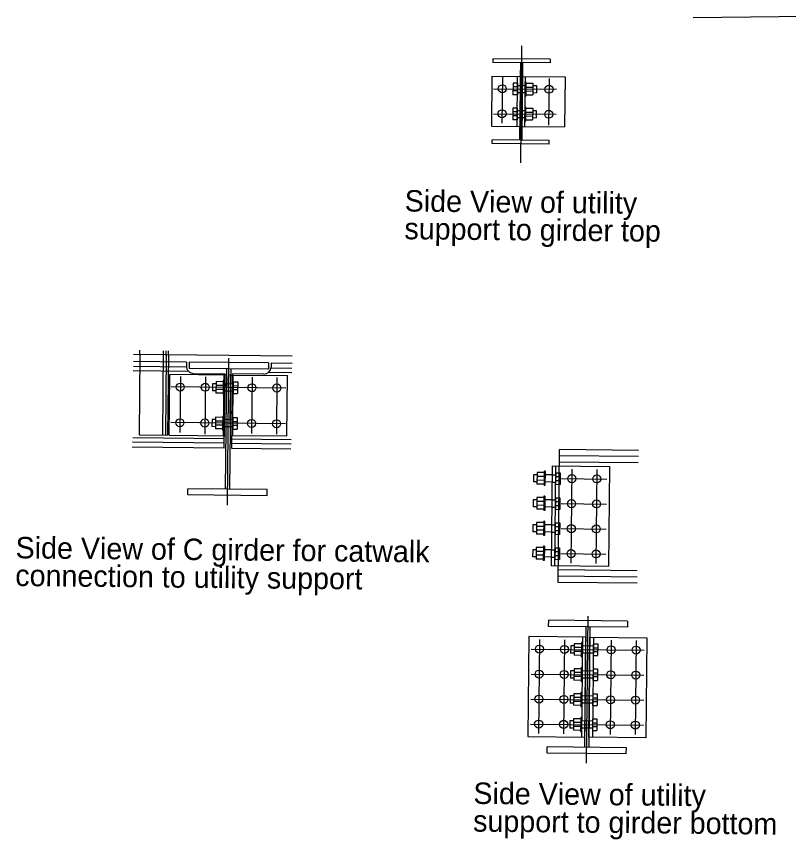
# Model space of a CAD drawing. Extents: x 632312 to 632425, y 378332 to 378413.
# Drawn here: x 632382.19 to 632391.2, y 378385.83 to 378395.43 of the extents above; entities that cross this region are included whole.
import ezdxf

# ---------------------------------------------------------------- set-up
doc = ezdxf.new("R2010")
doc.units = 0
for name, color, linetype in [('B_Boring', 7, 'Continuous'), ('B_Boring Annot', 7, 'Continuous'), ('R_Proposed Const Limits Cut', 7, 'Continuous'), ('R_Wall', 7, 'Continuous'), ('SHT_Dimensions', 7, 'Continuous'), ('USACE_Easement', 7, 'Continuous')]:
    doc.layers.add(name, color=color, linetype=linetype)

msp = doc.modelspace()

# ---------------------------------------------------------------- linework, layer by layer
at = {"layer": 'B_Boring'}
for p, q in [((632387.7503, 378394.9372), (632387.7498, 378394.8943)), ((632388.4177, 378394.9306), (632387.7503, 378394.9372)), ((632388.4173, 378394.8877), (632387.7498, 378394.8943)), ((632388.0713, 378394.8911), (632388.0623, 378393.9853)), ((632388.0959, 378394.8909), (632388.0869, 378393.9851)), ((632388.4177, 378394.9306), (632388.4173, 378394.8877)), ((632387.7382, 378394.7332), (632387.7324, 378394.1499)), ((632387.7382, 378394.7332), (632388.0697, 378394.7299)), ((632387.9855, 378394.6526), (632387.9842, 378394.5172)), ((632388.0376, 378394.6521), (632387.9855, 378394.6526)), ((632388.0326, 378394.1469), (632388.0384, 378394.7302)), ((632388.0376, 378394.6521), (632388.0363, 378394.5167)), ((632388.0943, 378394.7297), (632388.5923, 378394.7247)), ((632388.1255, 378394.7293), (632388.1197, 378394.146)), ((632388.1249, 378394.6668), (632388.1232, 378394.5002)), ((632388.1249, 378394.6668), (632388.1353, 378394.6667)), ((632388.1353, 378394.6667), (632388.1336, 378394.5001)), ((632388.1351, 378394.6511), (632388.2185, 378394.6503)), ((632388.2185, 378394.6503), (632388.2171, 378394.5149)), ((632388.5923, 378394.7247), (632388.5865, 378394.1414)), ((632388.0367, 378394.5618), (632387.9847, 378394.5623)), ((632388.0372, 378394.607), (632387.9851, 378394.6075)), ((632388.1342, 378394.5608), (632388.2176, 378394.56)), ((632388.1347, 378394.606), (632388.218, 378394.6052)), ((632388.2182, 378394.6242), (632388.2599, 378394.6238)), ((632388.2599, 378394.6238), (632388.259, 378394.5405)), ((632388.0363, 378394.5167), (632387.9842, 378394.5172)), ((632388.1232, 378394.5002), (632388.1336, 378394.5001)), ((632388.1338, 378394.5157), (632388.2171, 378394.5149)), ((632388.2174, 378394.5409), (632388.259, 378394.5405)), ((632387.9826, 378394.3609), (632387.9813, 378394.2255)), ((632388.0347, 378394.3604), (632387.9826, 378394.3609)), ((632388.122, 378394.3752), (632388.1203, 378394.2085)), ((632388.122, 378394.3752), (632388.1324, 378394.3751)), ((632388.1324, 378394.3751), (632388.1307, 378394.2084)), ((632388.0338, 378394.2701), (632387.9818, 378394.2706)), ((632388.0343, 378394.3153), (632387.9822, 378394.3158)), ((632388.0347, 378394.3604), (632388.0334, 378394.225)), ((632388.1313, 378394.2692), (632388.2147, 378394.2683)), ((632388.1318, 378394.3143), (632388.2151, 378394.3135)), ((632388.1322, 378394.3594), (632388.2156, 378394.3586)), ((632388.2156, 378394.3586), (632388.2142, 378394.2232)), ((632388.2153, 378394.3326), (632388.257, 378394.3321)), ((632388.257, 378394.3321), (632388.2561, 378394.2488)), ((632388.0334, 378394.225), (632387.9813, 378394.2255)), ((632388.1203, 378394.2085), (632388.1307, 378394.2084)), ((632388.1309, 378394.224), (632388.2142, 378394.2232)), ((632388.2145, 378394.2492), (632388.2561, 378394.2488)), ((632387.7324, 378394.1499), (632388.0639, 378394.1466)), ((632388.0885, 378394.1463), (632388.5865, 378394.1414)), ((632387.7404, 378393.9456), (632387.7408, 378393.9885)), ((632388.4083, 378393.9819), (632387.7408, 378393.9885)), ((632388.4079, 378393.939), (632388.4083, 378393.9819)), ((632388.4079, 378393.939), (632387.7404, 378393.9456)), ((632385.4086, 378391.4678), (632383.5584, 378391.4862)), ((632383.6308, 378391.4855), (632383.6313, 378391.5352)), ((632383.9381, 378391.4824), (632383.9385, 378391.529)), ((632383.9641, 378391.4821), (632383.9646, 378391.529)), ((632384.1753, 378391.3967), (632383.5576, 378391.4028)), ((632384.1753, 378391.3967), (632384.1748, 378391.3488)), ((632384.2065, 378391.3964), (632384.2058, 378391.3239)), ((632385.1315, 378391.3872), (632384.2065, 378391.3964)), ((632385.1315, 378391.3872), (632385.1307, 378391.3147)), ((632385.1627, 378391.3869), (632385.1622, 378391.339)), ((632385.1627, 378391.3869), (632385.4068, 378391.3845)), ((632384.1747, 378391.3384), (632383.5561, 378391.3445)), ((632385.1307, 378391.3147), (632384.2058, 378391.3239)), ((632384.632, 378389.9146), (632384.646, 378391.3195)), ((632384.6906, 378391.3191), (632384.6766, 378389.9141)), ((632385.1621, 378391.3286), (632385.4053, 378391.3261)), ((632383.973, 378390.5445), (632383.9801, 378391.2528)), ((632384.6452, 378391.2462), (632383.9801, 378391.2528)), ((632384.2573, 378391.2646), (632384.6245, 378391.261)), ((632384.6069, 378390.5382), (632384.614, 378391.2465)), ((632384.6159, 378390.3923), (632384.6245, 378391.261)), ((632384.6898, 378391.2457), (632385.355, 378391.2391)), ((632384.7108, 378391.2601), (632384.7022, 378390.3914)), ((632385.0781, 378391.2565), (632384.7108, 378391.2601)), ((632384.714, 378390.5371), (632384.7211, 378391.2454)), ((632385.3479, 378390.5308), (632385.355, 378391.2391)), ((632384.4775, 378391.1437), (632384.4767, 378391.0604)), ((632384.5192, 378391.1433), (632384.4775, 378391.1437)), ((632384.5195, 378391.1693), (632384.5181, 378391.0339)), ((632384.6023, 378391.1233), (632384.519, 378391.1242)), ((632384.6028, 378391.1685), (632384.5195, 378391.1693)), ((632384.6029, 378391.1841), (632384.6013, 378391.0175)), ((632384.6134, 378391.184), (632384.6029, 378391.1841)), ((632384.6134, 378391.184), (632384.6117, 378391.0173)), ((632384.7203, 378391.1673), (632384.7189, 378391.0319)), ((632384.7198, 378391.1222), (632384.7719, 378391.1217)), ((632384.7203, 378391.1673), (632384.7724, 378391.1668)), ((632384.7724, 378391.1668), (632384.771, 378391.0314)), ((632384.5184, 378391.0599), (632384.4767, 378391.0604)), ((632384.6014, 378391.0331), (632384.5181, 378391.0339)), ((632384.6019, 378391.0782), (632384.5186, 378391.079)), ((632384.6117, 378391.0173), (632384.6013, 378391.0175)), ((632384.7189, 378391.0319), (632384.771, 378391.0314)), ((632384.7194, 378391.077), (632384.7715, 378391.0765)), ((632384.4734, 378390.727), (632384.4726, 378390.6437)), ((632384.5151, 378390.7266), (632384.4734, 378390.727)), ((632384.5153, 378390.7527), (632384.514, 378390.6173)), ((632384.5986, 378390.7518), (632384.5153, 378390.7527)), ((632384.5988, 378390.7675), (632384.5971, 378390.6008)), ((632384.6092, 378390.7674), (632384.5988, 378390.7675)), ((632384.6092, 378390.7674), (632384.6076, 378390.6007)), ((632384.7162, 378390.7507), (632384.7148, 378390.6153)), ((632384.7162, 378390.7507), (632384.7682, 378390.7501)), ((632384.7682, 378390.7501), (632384.7669, 378390.6148)), ((632384.5142, 378390.6433), (632384.4726, 378390.6437)), ((632384.5973, 378390.6164), (632384.514, 378390.6173)), ((632384.5977, 378390.6616), (632384.5144, 378390.6624)), ((632384.5982, 378390.7067), (632384.5149, 378390.7075)), ((632384.7148, 378390.6153), (632384.7669, 378390.6148)), ((632384.7153, 378390.6604), (632384.7673, 378390.6599)), ((632384.7157, 378390.7055), (632384.7678, 378390.705)), ((632383.973, 378390.5445), (632384.6382, 378390.5379)), ((632384.6076, 378390.6007), (632384.5971, 378390.6008)), ((632385.3479, 378390.5308), (632384.6828, 378390.5375)), ((632384.6164, 378390.4506), (632383.5456, 378390.4613)), ((632384.7027, 378390.4497), (632385.3948, 378390.4429)), ((632384.6159, 378390.3923), (632383.5427, 378390.4029)), ((632384.7022, 378390.3914), (632385.3919, 378390.3846)), ((632388.5133, 378388.8256), (632388.5287, 378390.3756)), ((632389.4491, 378390.3664), (632388.5287, 378390.3756)), ((632389.4483, 378390.2939), (632388.528, 378390.3031)), ((632388.4435, 378390.1847), (632388.4319, 378389.0181)), ((632388.4435, 378390.1847), (632389.1101, 378390.1781)), ((632388.4735, 378389.0177), (632388.4851, 378390.1843)), ((632389.1101, 378390.1781), (632389.0985, 378389.0115)), ((632388.2237, 378390.0828), (632388.2229, 378389.9994)), ((632388.2654, 378390.0823), (632388.2237, 378390.0828)), ((632388.2656, 378390.1084), (632388.2643, 378389.973)), ((632388.3485, 378390.0624), (632388.2652, 378390.0632)), ((632388.349, 378390.1075), (632388.2656, 378390.1084)), ((632388.3491, 378390.1232), (632388.3475, 378389.9565)), ((632388.3595, 378390.1231), (632388.3491, 378390.1232)), ((632388.3595, 378390.1231), (632388.3579, 378389.9564)), ((632388.4424, 378390.0806), (632388.3591, 378390.0814)), ((632388.4839, 378390.0611), (632388.536, 378390.0606)), ((632388.4844, 378390.1062), (632388.5364, 378390.1057)), ((632388.5364, 378390.1057), (632388.5351, 378389.9703)), ((632388.2645, 378389.999), (632388.2229, 378389.9994)), ((632388.3476, 378389.9722), (632388.2643, 378389.973)), ((632388.3481, 378390.0173), (632388.2647, 378390.0181)), ((632388.3579, 378389.9564), (632388.3475, 378389.9565)), ((632388.4416, 378389.9973), (632388.3583, 378389.9981)), ((632388.483, 378389.9708), (632388.5351, 378389.9703)), ((632388.4835, 378390.0159), (632388.5356, 378390.0154)), ((632384.1911, 378389.8465), (632384.1918, 378389.919)), ((632385.1168, 378389.9098), (632384.1918, 378389.919)), ((632385.116, 378389.8373), (632385.1168, 378389.9098)), ((632385.116, 378389.8373), (632384.1911, 378389.8465)), ((632388.2208, 378389.7911), (632388.22, 378389.7078)), ((632388.2625, 378389.7907), (632388.2208, 378389.7911)), ((632388.2627, 378389.8167), (632388.2614, 378389.6813)), ((632388.3456, 378389.7708), (632388.2623, 378389.7716)), ((632388.3461, 378389.8159), (632388.2627, 378389.8167)), ((632388.3462, 378389.8315), (632388.3446, 378389.6649)), ((632388.3566, 378389.8314), (632388.3462, 378389.8315)), ((632388.3566, 378389.8314), (632388.355, 378389.6648)), ((632388.4395, 378389.7889), (632388.3562, 378389.7898)), ((632388.481, 378389.7694), (632388.5331, 378389.7689)), ((632388.4815, 378389.8145), (632388.5335, 378389.814)), ((632388.5335, 378389.814), (632388.5322, 378389.6786)), ((632388.2616, 378389.7074), (632388.22, 378389.7078)), ((632388.3447, 378389.6805), (632388.2614, 378389.6813)), ((632388.3452, 378389.7256), (632388.2618, 378389.7265)), ((632388.355, 378389.6648), (632388.3446, 378389.6649)), ((632388.4387, 378389.7056), (632388.3554, 378389.7064)), ((632388.4801, 378389.6792), (632388.5322, 378389.6786)), ((632388.4806, 378389.7243), (632388.5327, 378389.7238)), ((632388.2179, 378389.4995), (632388.2171, 378389.4161)), ((632388.2596, 378389.499), (632388.2179, 378389.4995)), ((632388.2598, 378389.5251), (632388.2585, 378389.3897)), ((632388.3427, 378389.4791), (632388.2594, 378389.4799)), ((632388.3432, 378389.5242), (632388.2598, 378389.5251)), ((632388.3433, 378389.5399), (632388.3417, 378389.3732)), ((632388.3537, 378389.5398), (632388.3433, 378389.5399)), ((632388.3537, 378389.5398), (632388.3521, 378389.3731)), ((632388.4366, 378389.4973), (632388.3533, 378389.4981)), ((632388.4781, 378389.4778), (632388.5302, 378389.4772)), ((632388.4786, 378389.5229), (632388.5306, 378389.5224)), ((632388.5306, 378389.5224), (632388.5293, 378389.387)), ((632388.2587, 378389.4157), (632388.2171, 378389.4161)), ((632388.3418, 378389.3888), (632388.2585, 378389.3897)), ((632388.3423, 378389.434), (632388.2589, 378389.4348)), ((632388.3521, 378389.3731), (632388.3417, 378389.3732)), ((632388.4358, 378389.4139), (632388.3525, 378389.4148)), ((632388.4772, 378389.3875), (632388.5293, 378389.387)), ((632388.4777, 378389.4326), (632388.5298, 378389.4321)), ((632388.215, 378389.2078), (632388.2142, 378389.1245)), ((632388.2567, 378389.2074), (632388.215, 378389.2078)), ((632388.2569, 378389.2334), (632388.2556, 378389.098)), ((632388.3398, 378389.1875), (632388.2565, 378389.1883)), ((632388.3403, 378389.2326), (632388.2569, 378389.2334)), ((632388.3404, 378389.2482), (632388.3388, 378389.0816)), ((632388.3508, 378389.2481), (632388.3404, 378389.2482)), ((632388.3508, 378389.2481), (632388.3492, 378389.0815)), ((632388.4337, 378389.2056), (632388.3504, 378389.2065)), ((632388.4752, 378389.1861), (632388.5273, 378389.1856)), ((632388.4757, 378389.2312), (632388.5277, 378389.2307)), ((632388.5277, 378389.2307), (632388.5264, 378389.0953)), ((632388.2558, 378389.1241), (632388.2142, 378389.1245)), ((632388.3389, 378389.0972), (632388.2556, 378389.098)), ((632388.3394, 378389.1423), (632388.256, 378389.1432)), ((632388.3492, 378389.0815), (632388.3388, 378389.0816)), ((632388.4329, 378389.1223), (632388.3496, 378389.1231)), ((632388.4743, 378389.0958), (632388.5264, 378389.0953)), ((632388.4748, 378389.141), (632388.5269, 378389.1405)), ((632389.0985, 378389.0115), (632388.4319, 378389.0181)), ((632389.4344, 378388.889), (632388.514, 378388.8981)), ((632389.4337, 378388.8165), (632388.5133, 378388.8256)), ((632388.398, 378388.3842), (632388.3973, 378388.3117)), ((632389.3223, 378388.3025), (632388.3973, 378388.3117)), ((632389.323, 378388.375), (632388.398, 378388.3842)), ((632389.323, 378388.375), (632389.3223, 378388.3025)), ((632388.8235, 378386.9024), (632388.8375, 378388.3073)), ((632388.8821, 378388.3069), (632388.8681, 378386.9019)), ((632388.1711, 378388.1948), (632388.1595, 378387.0282)), ((632388.8363, 378388.1882), (632388.1711, 378388.1948)), ((632388.7836, 378388.1262), (632388.7819, 378387.9595)), ((632388.7946, 378388.1886), (632388.783, 378387.022)), ((632388.794, 378388.1261), (632388.7836, 378388.1262)), ((632388.794, 378388.1261), (632388.7924, 378387.9594)), ((632388.8247, 378387.0215), (632388.8363, 378388.1882)), ((632388.8693, 378387.0211), (632388.8809, 378388.1877)), ((632388.8809, 378388.1877), (632389.5461, 378388.1811)), ((632388.9226, 378388.1873), (632388.911, 378387.0207)), ((632389.5461, 378388.1811), (632389.5345, 378387.0145)), ((632388.6582, 378388.0858), (632388.6574, 378388.0024)), ((632388.6999, 378388.0853), (632388.6582, 378388.0858)), ((632388.7001, 378388.1114), (632388.6988, 378387.976)), ((632388.783, 378388.0654), (632388.6997, 378388.0662)), ((632388.7834, 378388.1105), (632388.7001, 378388.1114)), ((632388.9218, 378388.1092), (632388.9204, 378387.9738)), ((632388.9213, 378388.064), (632388.9734, 378388.0635)), ((632388.9218, 378388.1092), (632388.9739, 378388.1086)), ((632388.9739, 378388.1086), (632388.9725, 378387.9733)), ((632388.699, 378388.002), (632388.6574, 378388.0024)), ((632388.7821, 378387.9751), (632388.6988, 378387.976)), ((632388.7825, 378388.0203), (632388.6992, 378388.0211)), ((632388.7924, 378387.9594), (632388.7819, 378387.9595)), ((632388.9204, 378387.9738), (632388.9725, 378387.9733)), ((632388.9209, 378388.0189), (632388.973, 378388.0184)), ((632388.7807, 378387.8345), (632388.779, 378387.6679)), ((632388.7911, 378387.8344), (632388.7807, 378387.8345)), ((632388.7911, 378387.8344), (632388.7895, 378387.6678)), ((632388.6553, 378387.7941), (632388.6545, 378387.7108)), ((632388.697, 378387.7937), (632388.6553, 378387.7941)), ((632388.6972, 378387.8197), (632388.6959, 378387.6843)), ((632388.7801, 378387.7738), (632388.6968, 378387.7746)), ((632388.7805, 378387.8189), (632388.6972, 378387.8197)), ((632388.9189, 378387.8175), (632388.9175, 378387.6821)), ((632388.9184, 378387.7724), (632388.9705, 378387.7719)), ((632388.9189, 378387.8175), (632388.971, 378387.817)), ((632388.971, 378387.817), (632388.9696, 378387.6816)), ((632388.6961, 378387.7104), (632388.6545, 378387.7108)), ((632388.7792, 378387.6835), (632388.6959, 378387.6843)), ((632388.7796, 378387.7286), (632388.6963, 378387.7295)), ((632388.7895, 378387.6678), (632388.779, 378387.6679)), ((632388.9175, 378387.6821), (632388.9696, 378387.6816)), ((632388.918, 378387.7272), (632388.9701, 378387.7267)), ((632388.7778, 378387.5429), (632388.7761, 378387.3762)), ((632388.7882, 378387.5428), (632388.7778, 378387.5429)), ((632388.7882, 378387.5428), (632388.7866, 378387.3761)), ((632388.6524, 378387.5024), (632388.6516, 378387.4191)), ((632388.6941, 378387.502), (632388.6524, 378387.5024)), ((632388.6943, 378387.5281), (632388.693, 378387.3927)), ((632388.7772, 378387.4821), (632388.6939, 378387.4829)), ((632388.7776, 378387.5272), (632388.6943, 378387.5281)), ((632388.916, 378387.5259), (632388.9146, 378387.3905)), ((632388.9155, 378387.4807), (632388.9676, 378387.4802)), ((632388.916, 378387.5259), (632388.9681, 378387.5253)), ((632388.9681, 378387.5253), (632388.9667, 378387.3899)), ((632388.6932, 378387.4187), (632388.6516, 378387.4191)), ((632388.7763, 378387.3918), (632388.693, 378387.3927)), ((632388.7767, 378387.437), (632388.6934, 378387.4378)), ((632388.7866, 378387.3761), (632388.7761, 378387.3762)), ((632388.9146, 378387.3905), (632388.9667, 378387.3899)), ((632388.9151, 378387.4356), (632388.9672, 378387.4351)), ((632388.6495, 378387.2108), (632388.6487, 378387.1275)), ((632388.6912, 378387.2104), (632388.6495, 378387.2108)), ((632388.6914, 378387.2364), (632388.6901, 378387.101)), ((632388.7743, 378387.1905), (632388.691, 378387.1913)), ((632388.7747, 378387.2356), (632388.6914, 378387.2364)), ((632388.7749, 378387.2512), (632388.7732, 378387.0846)), ((632388.7853, 378387.2511), (632388.7749, 378387.2512)), ((632388.7853, 378387.2511), (632388.7837, 378387.0845)), ((632388.9131, 378387.2342), (632388.9117, 378387.0988)), ((632388.9126, 378387.1891), (632388.9647, 378387.1886)), ((632388.9131, 378387.2342), (632388.9652, 378387.2337)), ((632388.9652, 378387.2337), (632388.9638, 378387.0983)), ((632388.6903, 378387.1271), (632388.6487, 378387.1275)), ((632388.7734, 378387.1002), (632388.6901, 378387.101)), ((632388.7738, 378387.1453), (632388.6905, 378387.1461)), ((632388.7837, 378387.0845), (632388.7732, 378387.0846)), ((632388.9117, 378387.0988), (632388.9638, 378387.0983)), ((632388.9122, 378387.1439), (632388.9643, 378387.1434)), ((632388.1595, 378387.0282), (632388.8247, 378387.0215)), ((632389.5345, 378387.0145), (632388.8693, 378387.0211)), ((632388.3826, 378386.8343), (632388.3833, 378386.9068)), ((632389.3083, 378386.8976), (632388.3833, 378386.9068)), ((632389.3076, 378386.8251), (632389.3083, 378386.8976)), ((632389.3076, 378386.8251), (632388.3826, 378386.8343))]:
    msp.add_line(p, q, dxfattribs=at)
for centre in [(632387.8599, 378394.5861), (632388.4053, 378394.5807), (632387.857, 378394.2945), (632388.4024, 378394.289), (632384.1021, 378391.1058), (632384.3938, 378391.1029), (632384.9384, 378391.0974), (632385.23, 378391.0945), (632384.098, 378390.6891), (632384.3896, 378390.6862), (632384.9342, 378390.6808), (632385.2259, 378390.6779), (632388.6712, 378390.0366), (632388.9628, 378390.0337), (632388.6683, 378389.745), (632388.9599, 378389.7421), (632388.6654, 378389.4533), (632388.957, 378389.4504), (632388.6625, 378389.1617), (632388.9541, 378389.1588), (632388.2932, 378388.0477), (632388.5849, 378388.0448), (632389.1294, 378388.0396), (632389.4211, 378388.0367), (632388.2903, 378387.7561), (632388.582, 378387.7532), (632389.1265, 378387.748), (632389.4182, 378387.7451), (632388.2874, 378387.4644), (632388.5791, 378387.4615), (632389.1236, 378387.4563), (632389.4153, 378387.4534), (632388.2845, 378387.1728), (632388.5762, 378387.1699), (632389.1207, 378387.1646), (632389.4124, 378387.1617)]:
    msp.add_circle(centre, 0.0469, dxfattribs=at)
for centre, start, end in [((632384.2581, 378391.348), 179.43036, 269.43036), ((632385.0789, 378391.3398), 269.43036, 359.43036)]:
    msp.add_arc(centre, 0.0833, start, end, dxfattribs=at)
at = {"layer": 'B_Boring Annot'}
msp.add_line((632391.6445, 378395.4298), (632390.0893, 378395.4142), dxfattribs=at)
at = {"layer": 'R_Proposed Const Limits Cut'}
for p, q in [((632388.0697, 378394.7299), (632388.0943, 378394.7297)), ((632388.0374, 378394.626), (632388.1245, 378394.6252)), ((632388.0365, 378394.5427), (632388.1236, 378394.5419)), ((632388.0345, 378394.3344), (632388.1216, 378394.3335)), ((632388.0336, 378394.251), (632388.1207, 378394.2502)), ((632388.0639, 378394.1466), (632388.0885, 378394.1463)), ((632383.6308, 378391.4855), (632383.6215, 378390.548)), ((632383.8975, 378390.5453), (632383.9073, 378391.5293)), ((632383.9381, 378391.4824), (632383.9287, 378390.5449)), ((632383.9641, 378391.4821), (632383.9548, 378390.5447)), ((632384.2012, 378391.2871), (632383.5535, 378391.2935)), ((632385.1346, 378391.2778), (632385.4027, 378391.2751)), ((632384.72, 378391.1413), (632384.6129, 378391.1423)), ((632384.7192, 378391.0579), (632384.6121, 378391.059)), ((632384.7159, 378390.7246), (632384.6088, 378390.7257)), ((632384.7151, 378390.6413), (632384.608, 378390.6424)), ((632383.6215, 378390.548), (632383.9548, 378390.5447)), ((632384.6169, 378390.5016), (632383.5486, 378390.5123)), ((632384.7033, 378390.5008), (632385.3977, 378390.4939)), ((632389.4476, 378390.2206), (632388.5273, 378390.2297)), ((632388.4424, 378390.0806), (632388.4841, 378390.0802)), ((632388.4416, 378389.9973), (632388.4833, 378389.9968)), ((632388.4395, 378389.7889), (632388.4812, 378389.7885)), ((632388.4387, 378389.7056), (632388.4804, 378389.7052)), ((632388.4366, 378389.4973), (632388.4783, 378389.4969)), ((632388.4358, 378389.4139), (632388.4775, 378389.4135)), ((632388.4337, 378389.2056), (632388.4754, 378389.2052)), ((632388.4329, 378389.1223), (632388.4746, 378389.1219)), ((632389.4351, 378388.9623), (632388.5148, 378388.9715)), ((632388.9215, 378388.0831), (632388.7936, 378388.0844)), ((632388.9207, 378387.9998), (632388.7928, 378388.0011)), ((632388.9186, 378387.7915), (632388.7907, 378387.7928)), ((632388.9178, 378387.7082), (632388.7899, 378387.7094)), ((632388.9157, 378387.4998), (632388.7878, 378387.5011)), ((632388.9149, 378387.4165), (632388.787, 378387.4178)), ((632388.9128, 378387.2082), (632388.7849, 378387.2094)), ((632388.912, 378387.1248), (632388.7841, 378387.1261))]:
    msp.add_line(p, q, dxfattribs=at)
at = {"layer": 'R_Wall'}
for p, q in [((632388.0855, 378395.0869), (632388.0719, 378393.7227)), ((632387.8613, 378394.7253), (632387.8559, 378394.1857)), ((632388.4065, 378394.707), (632388.4011, 378394.1622)), ((632387.759, 378394.5871), (632388.4929, 378394.5798)), ((632387.7561, 378394.2955), (632388.49, 378394.2882)), ((632384.6524, 378389.7292), (632384.6695, 378391.4437)), ((632384.1034, 378391.2285), (632384.0969, 378390.5743)), ((632384.395, 378391.2256), (632384.3883, 378390.5546)), ((632384.9396, 378391.2202), (632384.9331, 378390.5637)), ((632385.2312, 378391.2173), (632385.2247, 378390.5577)), ((632385.3356, 378391.0935), (632383.9951, 378391.1068)), ((632385.3297, 378390.6769), (632383.9906, 378390.6902)), ((632388.6723, 378390.1476), (632388.6614, 378389.0507)), ((632388.9639, 378390.1447), (632388.953, 378389.0478)), ((632388.5519, 378390.0378), (632389.0785, 378390.0326)), ((632388.549, 378389.7462), (632389.0756, 378389.7409)), ((632388.5461, 378389.4545), (632389.0727, 378389.4493)), ((632388.5432, 378389.1629), (632389.0698, 378389.1576)), ((632388.844, 378386.717), (632388.861, 378388.4314)), ((632388.2943, 378388.1587), (632388.2834, 378387.0617)), ((632388.586, 378388.1558), (632388.5751, 378387.0588)), ((632389.1305, 378388.1506), (632389.1196, 378387.0536)), ((632389.4222, 378388.1477), (632389.4113, 378387.0507)), ((632388.1984, 378388.0487), (632389.5159, 378388.0356)), ((632388.1955, 378387.757), (632389.513, 378387.7439)), ((632388.1926, 378387.4654), (632389.5101, 378387.4523)), ((632388.1897, 378387.1737), (632389.5072, 378387.1606))]:
    msp.add_line(p, q, dxfattribs=at)
at = {"layer": 'SHT_Dimensions'}
for p, q in [((632388.0704, 378394.8028), (632388.0632, 378394.0841)), ((632388.0949, 378394.7921), (632388.0878, 378394.0838)), ((632385.0856, 378391.3877), (632384.2523, 378391.3959)), ((632384.6395, 378390.6733), (632384.6453, 378391.2562)), ((632384.6841, 378390.6729), (632384.6899, 378391.2557)), ((632388.4844, 378390.1062), (632388.483, 378389.9708)), ((632388.4815, 378389.8145), (632388.4801, 378389.6792)), ((632388.4786, 378389.5229), (632388.4772, 378389.3875)), ((632388.4757, 378389.2312), (632388.4743, 378389.0958))]:
    msp.add_line(p, q, dxfattribs=at)

# ---------------------------------------------------------------- texts
at = {"layer": 'USACE_Easement'}
for s, p in [('Side View of utility ', (632386.7202, 378393.1543)), ('support to girder top', (632386.717, 378392.8308)), ('Side View of C girder for catwalk ', (632382.1795, 378389.1077)), ('connection to utility support', (632382.1763, 378388.7842)), ('Side View of utility ', (632387.5222, 378386.2423)), ('support to girder bottom', (632387.519, 378385.9188))]:
    msp.add_text(s, height=0.25, rotation=359.43036, dxfattribs=at).set_placement(p)

doc.saveas('drawing.dxf')
